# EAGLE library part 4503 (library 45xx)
Tri-state hex BUFFER, 74C367, 80C97
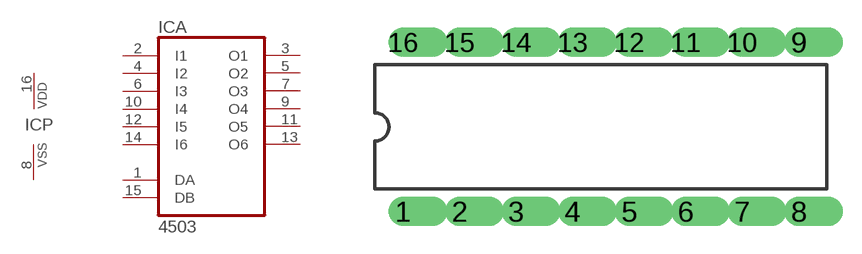
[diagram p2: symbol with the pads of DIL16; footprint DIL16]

Designator prefix IC; gates A=4503 P=PWRN

## 4503N  [DIL16]
1  A:DA  in
2  A:I1  in
3  A:O1  out
4  A:I2  in
5  A:O2  out
6  A:I3  in
7  A:O3  out
8  P:VSS  pwr
9  A:O4  out
10  A:I4  in
11  A:O5  out
12  A:I5  in
13  A:O6  out
14  A:I6  in
15  A:DB  in
16  P:VDD  pwr

## Footprint DIL16 (pad centres in mm)
Dual In Line
drill 0.813 offset: 1 -8.89,-3.81; 2 -6.35,-3.81; 3 -3.81,-3.81; 4 -1.27,-3.81; 5 1.27,-3.81; 6 3.81,-3.81; 7 6.35,-3.81; 8 8.89,-3.81; 9 8.89,3.81; 10 6.35,3.81; 11 3.81,3.81; 12 1.27,3.81; 13 -1.27,3.81; 14 -3.81,3.81; 15 -6.35,3.81; 16 -8.89,3.81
